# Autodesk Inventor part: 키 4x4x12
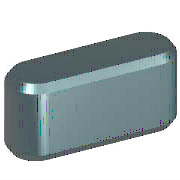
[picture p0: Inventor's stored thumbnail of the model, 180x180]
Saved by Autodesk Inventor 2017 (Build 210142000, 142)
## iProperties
IsCustomPart: 1
Created: 2012-02
Part Number: 키 4x4x12
Material: 강철, 연강
Description: 키 및 해당 키홈
Document SubType Name: Modeling
Standard: KS B 1311
Designer: mduedu
Standards Organization: KS
Language: ko-KR
Size Designation: 4 x 4 x 12
Categories: <MemberInstance><Categories><Category DisplayName="샤프트 부품" InternalName="7f7aeb1f-a693-4053-b835-cee3144e0d98" Mnemonic="SHFT"><Category DisplayName="키" Interna
Density: 1 g/cm^3
Appearance: 노란색
Author: mduedu
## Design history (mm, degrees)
workplane "Work Plane1"
workplane "Work Plane2"
sketch "스케치1"
  geometry: L1 (2, 2)-(10, 2); L2 (10, -2)-(2, -2); L3 (0, 9.4)-(0, -7.4) reference; L4 (-5, 0)-(30, 0) reference; L5 (12, 0)-(12, 7); A1 r 2 centre (2, 0) between (2, 2) and (2, -2); A2 r 2 centre (10, 0) between (10, -2) and (10, 2)
  constraints: 6 end point, 5 point on circle, 4 tangent, 3 point on line, 2 centre point, 1 horizontal, 1 parallel, 1 perpendicular
  dimensions: "d0" = 2 radius of A1 (= 0.5 x PB); "d13" = 2 radius of A2 (= 0.5 x PB); "d14" = 12 distance between parallel lines of L5 L3 (= NLG)
extrude "본체1" new body sketch "스케치1" taper "d3" = 0 deg; stored distance "d4" = 10
workplane "Work Plane3"
body "Solid1"
chamfer "모따기1" distance "d8" = 0.25 (= PHH); stored, may be unused: second distance "d9" = 0.25 (= PHH), angle "d15" = 45 deg
other parameters: "d1" = -2.5 (= -PNT), "d2" = 1.5 (= PH - PNT), "NLG" = 12 [user parameter; used in 3 equation terms], "PB" = 4 [user parameter; used in 2 equation terms], "PNT" = 2.5 [user parameter; used in 2 equation terms], "PH" = 4 [user parameter; used in 1 equation term], "PHH" = 0.25 [user parameter; used in 2 equation terms], "d10" = 0, "d16" = 0, "d17" = 0, "d18" = 0, "PLB2" = 12 (= NLG) [user parameter], "WDMAX" = 12 [user parameter], "PLB1" = 12 (= NLG) [user parameter], "RR" = 0.08 [user parameter], "PUEB" = 1.8 [user parameter]
